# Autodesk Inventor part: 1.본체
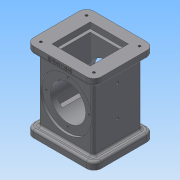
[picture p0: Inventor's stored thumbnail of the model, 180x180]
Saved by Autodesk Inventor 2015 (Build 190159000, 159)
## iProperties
Created: 2017-08
Part Number: 1.본체
Material: 일반
Document SubType Name: Modeling
Designer: owner
Density: 1 g/cm^3
Appearance: 기본값
Author: owner
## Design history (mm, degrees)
sketch "스케치1"
  geometry: L1 (-41, -46)-(41, -46); L2 (41, -46)-(41, 46); L3 (41, 46)-(-41, 46); L4 (-41, 46)-(-41, -46); L5 (-41, -46)-(41, 46); L6 (41, -46)-(-41, 46); 1 further point
  constraints: 12 end point, 2 midpoint, 2 parallel, 1 horizontal, 1 perpendicular
  dimensions: "d0" = 92 distance between parallel lines of L1 L3; "d1" = 82 distance between parallel lines of L4 L2
extrude "돌출1" new body sketch "스케치1" distance "d2" = 10; taper "d3" = 0 deg
sketch "스케치2"
  geometry: L1 (33, 37)-(-33, 37); L2 (-33, 37)-(-33, -37); L3 (-33, -37)-(33, -37); L4 (33, -37)-(33, 37); L5 (33, 37)-(-33, -37); L6 (-33, 37)-(33, -37); 1 further point
  constraints: 12 end point, 2 midpoint, 2 parallel, 1 horizontal, 1 perpendicular
  dimensions: "d4" = 74 distance between parallel lines of L1 L3; "d5" = 66 distance between parallel lines of L4 L2
extrude "돌출2" join sketch "스케치2" distance "d6" = 88; taper "d7" = 0 deg
sketch "스케치3"
  geometry: L1 (41, 46)-(-41, 46) reference; L2 (-41, 46)-(-41, -46) reference; L3 (-41, -46)-(41, -46) reference; L4 (41, -46)-(41, 46) reference; 1 further point
extrude "돌출3" join sketch "스케치3" distance "d8" = 10; taper "d9" = 0 deg
sketch "스케치5"
  geometry: L1 (26, -26)-(-26, -26); L2 (-26, -26)-(-26, 26); L3 (-26, 26)-(26, 26); L4 (26, 26)-(26, -26); L5 (26, -26)-(-26, 26); L6 (-26, -26)-(26, 26); 1 further point
  constraints: 12 end point, 2 midpoint, 2 parallel, 1 horizontal, 1 perpendicular
  dimensions: "d14" = 52 distance between parallel lines of L4 L2; "d15" = 52 distance between parallel lines of L1 L3 (= d14)
extrude "돌출5" cut sketch "스케치5" distance "d16" = 8; taper "d17" = 0 deg
sketch "스케치6"
  geometry: L1 (24, -24)-(-24, -24); L2 (-24, -24)-(-24, 24); L3 (-24, 24)-(24, 24); L4 (24, 24)-(24, -24); L5 (24, -24)-(-24, 24); L6 (-24, -24)-(24, 24); 1 further point
  constraints: 12 end point, 2 midpoint, 2 parallel, 1 horizontal, 1 perpendicular
  dimensions: "d18" = 48 distance between parallel lines of L4 L2; "d19" = 48 distance between parallel lines of L1 L3 (= d18)
extrude "돌출6" cut sketch "스케치6" distance "d20" = 16; taper "d21" = 0 deg
sketch "스케치7"
  geometry: L1 (-33, 10)-(-33, 98) reference; L2 (33, 10)-(33, 98) reference; L3 (-33, 54)-(33, 54); L4 (24, 0)-(-24, 0) reference; L5 (-33, 89)-(-30, 89); L6 (-30, 89)-(-30, 54); 1 further point
  constraints: 6 end point, 2 midpoint, 2 perpendicular, 2 point on line, 1 horizontal
  dimensions: "d22" = 54 distance between parallel lines of L4 L3; "d23" = 3 distance between parallel lines of L6 L1; "d24" = 70 diameter of L5.start L3
revolve "회전1" sketch "스케치7" stored, may be unused: angle "d25" = 90 deg
sketch "스케치8"
  geometry: C1 r 35 at (0, 0) reference; C2 r 24 at (0, 0); 1 further point
  constraints: 1 centre point, 1 coincident
  dimensions: "d26" = 48 diameter of C2
extrude "돌출7" cut sketch "스케치8" stored distance "d27" = 16; taper "d28" = 0 deg
sketch "스케치9" dims "d30" = 58
  geometry: L1 (0, 0)-(0, 29); 3 further points
  constraints: 2 coincident, 2 end point, 1 vertical, 1 vertical alignment, 2 other
hole "구멍1" sketch "스케치9" at (0, 29) diameter "d31" = 3.242; stored, may be unused: countersink angle "d35" = 90 deg, drill point angle "d37" = 118 deg; dims "d32" = 4, "d33" = 4, "d34" = 2, "d36" = 6
sketch "스케치10"
  geometry: L1 (31, -36)-(-31, -36); L2 (-31, -36)-(-31, 36); L3 (-31, 36)-(31, 36); L4 (31, 36)-(31, -36); L5 (31, -36)-(-31, 36); L6 (-31, -36)-(31, 36); 5 further points
  constraints: 12 end point, 4 coincident, 2 midpoint, 2 parallel, 1 horizontal, 1 perpendicular
  dimensions: "d41" = 62 distance between parallel lines of L4 L2; "d42" = 72 distance between parallel lines of L1 L3
hole "구멍2" sketch "스케치10" at (-31, 36), (31, 36), (31, -36), (-31, -36) diameter "d43" = 3.242; stored, may be unused: countersink angle "d47" = 90 deg, drill point angle "d49" = 118 deg; dims "d44" = 4, "d45" = 4, "d46" = 2, "d48" = 6
sketch "스케치12"
  geometry: L1 (22, -22)-(-22, -22); L2 (-22, -22)-(-22, 22); L3 (-22, 22)-(22, 22); L4 (22, 22)-(22, -22); L5 (22, -22)-(-22, 22); L6 (-22, -22)-(22, 22); 1 further point
  constraints: 12 end point, 2 midpoint, 2 parallel, 1 horizontal, 1 perpendicular
  dimensions: "d50" = 44 distance between parallel lines of L4 L2; "d51" = 44 distance between parallel lines of L1 L3
extrude "돌출8" cut sketch "스케치12" distance "d52" = 64; taper "d53" = 0 deg
fillet "모깎기1" dims "d54" = 3, "d55" = 10
sketch "스케치13"
  geometry: L1 (31, 36)-(-31, 36); L2 (-31, 36)-(-31, -36); L3 (-31, -36)-(31, -36); L4 (31, -36)-(31, 36); L5 (31, 36)-(-31, -36); L6 (-31, 36)-(31, -36); 5 further points
  constraints: 12 end point, 4 coincident, 2 midpoint, 2 parallel, 1 horizontal, 1 perpendicular
  dimensions: "d56" = 72 distance between parallel lines of L1 L3; "d57" = 62 distance between parallel lines of L4 L2
hole "구멍3" sketch "스케치13" at (-31, -36), (-31, 36), (31, 36), (31, -36) diameter "d58" = 3.242; stored, may be unused: countersink angle "d62" = 90 deg, drill point angle "d64" = 118 deg; dims "d59" = 4, "d60" = 4, "d61" = 2, "d63" = 6
sketch "스케치14"
  geometry: L1 (-0.196, 10)-(61.804, 10) reference; L2 (30.804, -98)-(30.804, 10); L3 (-0.196, -98)-(61.804, -98) reference; 2 further points
  constraints: 2 end point, 2 point on line, 1 midpoint
  dimensions: "d65" = 38 distance from line of point (30.804, -60) L3; "d66" = 42 distance of point (30.804, -60) point (30.804, -18)
hole "구멍4" sketch "스케치14" at (30.804, -60), (30.804, -18) diameter "d67" = 4.134; stored, may be unused: countersink angle "d71" = 90 deg, drill point angle "d73" = 118 deg; dims "d68" = 10, "d69" = 4, "d70" = 2, "d72" = 20.95
sketch "스케치15"
  geometry: L1 (-10, 7)-(-10, 0) reference; L2 (72, 7)-(82, 7) reference; 2 further points
  constraints: 1 other
  dimensions: "d74" = 46 distance from line of point (36, 3) L1; "d75" = 4 distance from line of L2 point (36, 3)
feature "엠보싱1" sketch "스케치15" dims "d9" = 0, "d76" = 0.5, "d77" = 0
node "솔리드1"
pattern_circular "원형 패턴1" dims angle "d39" = 360 deg
mirror "대칭1"
mirror "대칭2"
